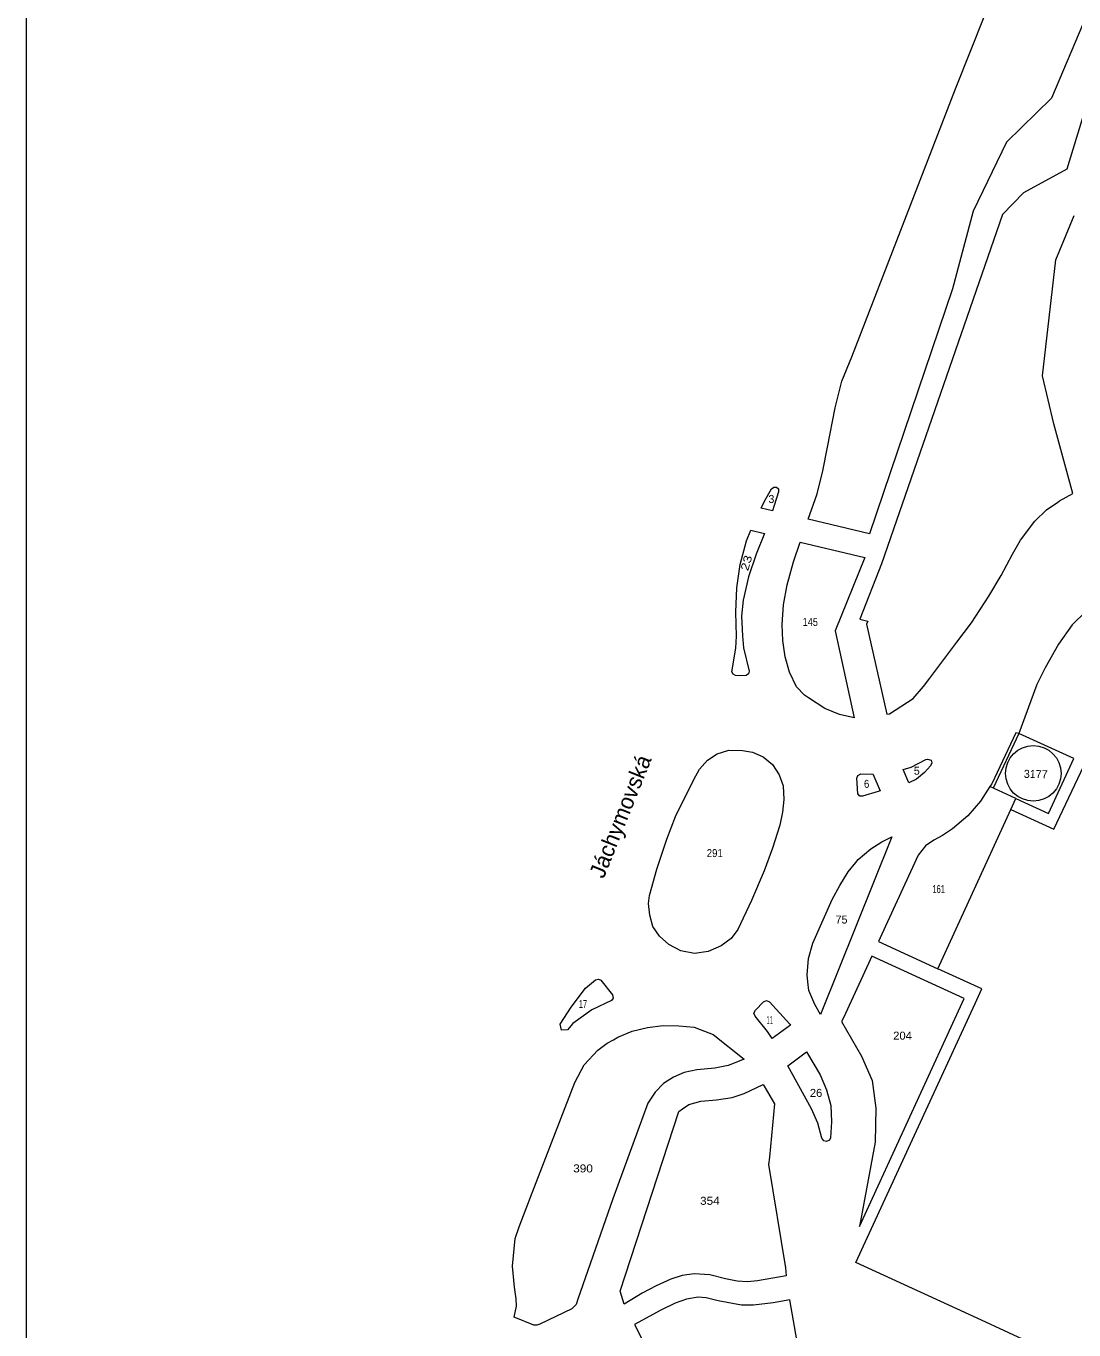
# Model space of a CAD drawing. Extents: x -843400 to -842830, y -1002860 to -1002082.
# Drawn here: x -843400.1 to -843269.1, y -1002620.7 to -1002457.7 of the extents above; entities that cross this region are included whole.
import ezdxf
from ezdxf.enums import TextEntityAlignment as Align

# ---------------------------------------------------------------- set-up
doc = ezdxf.new("R2010")
doc.units = 0
doc.header["$LTSCALE"] = 0.4
doc.layers.add('20', color=7, linetype='Continuous')
for name, color, linetype, lineweight in [('32', 7, 'Continuous', 13), ('35', 7, 'Continuous', 13), ('36', 7, 'Continuous', 13), ('38', 7, 'Continuous', 13), ('43', 7, 'Continuous', 13), ('44', 7, 'Continuous', 13)]:
    doc.layers.add(name, color=color, linetype=linetype, lineweight=lineweight)

msp = doc.modelspace()

# ---------------------------------------------------------------- linework, layer by layer
at = {"layer": '32'}
msp.add_lwpolyline([(-843229.79, -1002541.74), (-843230.26, -1002541.8), (-843232.13, -1002541.23), (-843242.89, -1002535.94), (-843244.35, -1002531.36), (-843249.31, -1002529.54), (-843252.84, -1002528.66), (-843256.77, -1002528.18), (-843260.3, -1002528.06), (-843262.55, -1002528.32), (-843264.95, -1002529.25), (-843267.58, -1002530.82), (-843269.35, -1002532.51), (-843271.05, -1002534.95), (-843272.73, -1002537.9), (-843273.74, -1002539.98), (-843276.02, -1002546.1), (-843276.39, -1002546.03), (-843279.4, -1002552.38), (-843279.629, -1002552.744)], dxfattribs=at)
at = {"layer": '36'}
msp.add_circle((-843274.196, -1002551.0828), 3.4752, dxfattribs=at)
at = {"layer": '38'}
for points in [[(-843276.364, -1002554.235), (-843272.28, -1002556.1), (-843269.15, -1002549.23), (-843276.02, -1002546.1), (-843279.2, -1002552.94)], [(-843276.99, -1002555.6), (-843271.63, -1002558.06), (-843267.9, -1002550.12), (-843233.22, -1002566.07), (-843229.49, -1002557.91), (-843217.51, -1002563.41), (-843214.18, -1002568.18), (-843216.63, -1002573.61), (-843205.49, -1002578.73), (-843233.93, -1002640.83), (-843246.1, -1002635.37), (-843247.52, -1002638.46), (-843254.81, -1002635.1), (-843253.51, -1002632), (-843281.23, -1002619.2), (-843296.36, -1002612.22), (-843281.484, -1002579.845), (-843280.65, -1002578.03), (-843286.12, -1002575.52)]]:
    msp.add_lwpolyline(points, dxfattribs=at)
at = {"layer": '43'}
for points in [[(-843217.19, -1002333.18), (-843226.47, -1002357.28), (-843239.13, -1002388.59), (-843250.24, -1002414.68), (-843261.68, -1002442.44), (-843271.91, -1002466.67), (-843277.55, -1002472.17), (-843281.73, -1002480.82), (-843284.3, -1002490.53), (-843294.657, -1002521.152), (-843302.333, -1002519.323), (-843301.23, -1002516.16), (-843300.52, -1002513.26), (-843299.93, -1002510.29), (-843298.98, -1002505.38), (-843298.14, -1002502.05), (-843296.89, -1002499.02), (-843283.93, -1002465.53), (-843273.11, -1002438.25), (-843261.95, -1002409.61), (-843251.14, -1002382.13), (-843240.02, -1002353.81), (-843228.82, -1002325.16)], [(-843265.4, -1002460.44), (-843269.723, -1002474.597), (-843270.02, -1002475.57), (-843275.43, -1002478.53), (-843278.04, -1002481.24), (-843293.19, -1002524.91), (-843295.89, -1002531.79), (-843294.89, -1002532.07), (-843295.03, -1002532.42), (-843292.51, -1002543.7), (-843292.17, -1002543.64), (-843289.21, -1002541.71), (-843287.93, -1002540.24), (-843287.14, -1002539.18), (-843283.77, -1002534.69), (-843281.94, -1002532.27), (-843279.74, -1002528.93), (-843278.22, -1002526.33), (-843276.8, -1002523.67), (-843275.81, -1002521.95), (-843274, -1002519.56), (-843272.55, -1002518.16), (-843271.14, -1002517.18), (-843270.91, -1002517.02), (-843269.25, -1002516.08), (-843269.62, -1002514.74), (-843271.64, -1002507.39), (-843273.057, -1002501.387), (-843271.39, -1002486.91), (-843269.09, -1002481.33)]]:
    msp.add_lwpolyline(points, dxfattribs=at)
for points in [[(-843308.215, -1002517.921), (-843307.78, -1002517.06), (-843306.93, -1002515.52), (-843306.65, -1002515.29), (-843306.3, -1002515.3), (-843306.05, -1002515.52), (-843306.04, -1002515.9), (-843306.58, -1002517.6), (-843306.806, -1002518.256)], [(-843310.84, -1002524.97), (-843310.05, -1002522.02), (-843309.517, -1002520.694), (-843307.799, -1002521.104), (-843308.84, -1002523.69), (-843309.81, -1002526.53), (-843310.45, -1002529.45), (-843310.65, -1002531.43), (-843310.56, -1002533.89), (-843310.4, -1002535.38), (-843309.73, -1002538.3), (-843309.81, -1002538.64), (-843310.09, -1002538.83), (-843310.77, -1002538.88), (-843311.41, -1002538.86), (-843311.73, -1002538.69), (-843311.86, -1002538.38), (-843311.38, -1002535.42), (-843311.3, -1002533.95), (-843311.38, -1002530.92), (-843311.24, -1002527.91)], [(-843303.326, -1002522.17), (-843295.266, -1002524.091), (-843298.95, -1002533.28), (-843296.58, -1002544.14), (-843298.44, -1002543.73), (-843300.26, -1002542.96), (-843302.3, -1002541.65), (-843302.8, -1002541.32), (-843303.8, -1002540.27), (-843304.66, -1002538.45), (-843305.2, -1002536.52), (-843305.52, -1002534.49), (-843305.6, -1002532.49), (-843305.42, -1002530.01), (-843304.98, -1002527.52), (-843304.19, -1002524.65)], [(-843305.96, -1002551.26), (-843305.48, -1002552.63), (-843305.36, -1002554.35), (-843305.53, -1002555.95), (-843305.9, -1002557.54), (-843306.81, -1002560.44), (-843307.83, -1002563.26), (-843309.4, -1002566.99), (-843311.12, -1002570.58), (-843311.961, -1002571.74), (-843313.22, -1002572.63), (-843314.82, -1002573.33), (-843316.56, -1002573.59), (-843318.27, -1002573.26), (-843319.76, -1002572.46), (-843320.9, -1002571.45), (-843321.76, -1002570.23), (-843322.14, -1002568.8), (-843322.29, -1002567.33), (-843322.19, -1002566.36), (-843321.25, -1002563.05), (-843320.02, -1002559.3), (-843318.93, -1002556.48), (-843316.61, -1002551.84), (-843315.93, -1002550.54), (-843314.94, -1002549.44), (-843313.71, -1002548.63), (-843312.27, -1002548.19), (-843310.55, -1002548.22), (-843309.3, -1002548.44), (-843307.96, -1002549), (-843306.81, -1002549.98)], [(-843290.45, -1002550.6), (-843289.47, -1002550.29), (-843287.63, -1002549.33), (-843287.44, -1002549.3), (-843286.97, -1002549.45), (-843286.86, -1002549.77), (-843287.03, -1002550.15), (-843287.78, -1002550.97), (-843288.8, -1002551.79), (-843289.74, -1002552.26)], [(-843293.333, -1002553.27), (-843293.57, -1002553.33), (-843295.53, -1002553.94), (-843295.89, -1002553.93), (-843296.11, -1002553.63), (-843296.27, -1002551.68), (-843296.14, -1002551.33), (-843295.76, -1002551.12), (-843294.37, -1002551.17), (-843294.235, -1002551.16)], [(-843286.12, -1002575.52), (-843276.99, -1002555.6), (-843276.364, -1002554.235), (-843279.629, -1002552.744), (-843280.78, -1002554.57), (-843282.4, -1002556.37), (-843284.31, -1002558.01), (-843285.54, -1002558.84), (-843286.63, -1002559.45), (-843287.68, -1002560.14), (-843288.59, -1002561.29), (-843293.11, -1002571.17), (-843293.547, -1002572.116)], [(-843291.88, -1002559.03), (-843300.79, -1002581.214), (-843301.5, -1002579.98), (-843302.24, -1002578.21), (-843302.37, -1002577.12), (-843302.48, -1002576.27), (-843302.3, -1002574.21), (-843301.74, -1002572.3), (-843299.35, -1002566.84), (-843298.39, -1002565.08), (-843297.33, -1002563.38), (-843296.39, -1002562.23), (-843296.08, -1002561.85), (-843294.51, -1002560.5), (-843293.12, -1002559.65)], [(-843282.848, -1002579.22), (-843294.386, -1002573.932), (-843294.81, -1002574.85), (-843297.94, -1002581.63), (-843298.162, -1002582.112), (-843295.69, -1002586.432), (-843294.333, -1002589.471), (-843293.892, -1002592.917), (-843293.956, -1002597.164), (-843295.937, -1002607.708)], [(-843333.17, -1002583.18), (-843333.32, -1002582.45), (-843331.98, -1002580.29), (-843330.19, -1002577.93), (-843328.9, -1002576.87), (-843328.55, -1002576.79), (-843328.24, -1002576.94), (-843326.79, -1002578.76), (-843326.7, -1002579.17), (-843326.94, -1002579.49), (-843329.36, -1002580.62), (-843331.75, -1002582.35), (-843332.44, -1002583.14)], [(-843304.56, -1002582.57), (-843306.85, -1002584.22), (-843307.42, -1002583.34), (-843308.96, -1002581.44), (-843309.11, -1002581.07), (-843308.94, -1002580.69), (-843307.92, -1002579.66), (-843307.56, -1002579.49), (-843307.17, -1002579.63), (-843304.63, -1002582.45)], [(-843315.84, -1002583.1), (-843314.23, -1002583.73), (-843310.33, -1002586.8), (-843312.33, -1002587.6), (-843314.02, -1002587.94), (-843316.27, -1002588.14), (-843317.82, -1002588.48), (-843319.19, -1002589.04), (-843320.42, -1002589.86), (-843321.48, -1002590.95), (-843322.37, -1002592.3), (-843326.76, -1002604.25), (-843331.13, -1002616.8), (-843331.35, -1002617.48), (-843331.87, -1002618.03), (-843335.86, -1002619.92), (-843336.25, -1002620.06), (-843336.61, -1002620.04), (-843339.1, -1002619.06), (-843338.81, -1002617.69), (-843338.85, -1002616.75), (-843339.06, -1002615.29), (-843339.28, -1002612.68), (-843338.96, -1002609.24), (-843338.48, -1002607.78), (-843337.05, -1002604.04), (-843335.12, -1002599.1), (-843331.5, -1002589.71), (-843330.32, -1002587.51), (-843328.64, -1002585.67), (-843327.46, -1002584.81), (-843326.68, -1002584.38), (-843326.14, -1002584.07), (-843324.35, -1002583.32), (-843322.43, -1002582.84), (-843320.48, -1002582.59), (-843318.52, -1002582.62), (-843316.59, -1002582.81)], [(-843302.53, -1002585.9), (-843300.84, -1002588.78), (-843300.04, -1002590.65), (-843299.52, -1002592.61), (-843299.44, -1002594.62), (-843299.53, -1002596.62), (-843299.67, -1002596.93), (-843300.03, -1002597.1), (-843300.39, -1002597.03), (-843300.63, -1002596.7), (-843301.14, -1002594.8), (-843301.92, -1002593), (-843304.89, -1002587.65)], [(-843318.52, -1002593.34), (-843318.03, -1002593), (-843317.26, -1002592.47), (-843315.77, -1002592.07), (-843313.81, -1002591.91), (-843311.85, -1002591.58), (-843310.34, -1002591.09), (-843307.97, -1002589.97), (-843307.44, -1002590.87), (-843306.53, -1002592.4), (-843307.19, -1002599.06), (-843307.28, -1002599.97), (-843305.19, -1002612.89), (-843305.07, -1002613.89), (-843308.69, -1002614.51), (-843309.94, -1002614.62), (-843311.21, -1002614.57), (-843312.68, -1002614.27), (-843314.62, -1002613.77), (-843316.59, -1002613.63), (-843318.1, -1002613.84), (-843319.49, -1002614.3), (-843321.34, -1002615.14), (-843323.1, -1002616.06), (-843325.33, -1002617.43), (-843325.85, -1002615.8)], [(-843296.15, -1002651.57), (-843299.74, -1002646.72), (-843303.02, -1002626.16), (-843304.63, -1002616.89), (-843306.72, -1002617.26), (-843309.18, -1002617.56), (-843310.69, -1002617.56), (-843313.59, -1002617.01), (-843315.08, -1002616.64), (-843316.08, -1002616.56), (-843317.56, -1002616.79), (-843318.98, -1002617.3), (-843320.76, -1002618.18), (-843324.05, -1002619.99), (-843315.52, -1002637.02), (-843307.41, -1002653.43), (-843302.74, -1002658.55), (-843296.19, -1002662.79), (-843284.8, -1002667.54), (-843278.01, -1002669.84), (-843275.318, -1002663.859), (-843274.325, -1002661.635)]]:
    msp.add_lwpolyline(points, close=True, dxfattribs=at)
at = {"layer": '44'}
msp.add_lwpolyline([(-842830.097, -1002859.997), (-842830.097, -1002081.989), (-843400.094, -1002081.989), (-843400.094, -1002859.997)], close=True, dxfattribs=at)

# ---------------------------------------------------------------- texts
at = {"layer": '20'}
msp.add_text('Jáchymovská', height=2, rotation=68.169, dxfattribs=at).set_placement((-843327.903, -1002564.336))
at = {"layer": '35'}
msp.add_text('3177', height=1, rotation=358.734, dxfattribs=at).set_placement((-843273.903, -1002551.6718), align=Align.CENTER)
at = {"layer": '43'}
for s, p in [('3', (-843307.309, -1002517.278)), ('5', (-843289.135, -1002551.253)), ('75', (-843298.91, -1002569.855))]:
    msp.add_text(s, height=1, dxfattribs=at).set_placement(p)
at = {"layer": '43', "width": 1.3}
msp.add_text('23', height=1, rotation=73.836, dxfattribs=at).set_placement((-843309.855, -1002525.845))
at = {"layer": '43'}
for s, width, p in [('145', 0.85, (-843303.019, -1002532.656)), ('6', 0.9, (-843295.362, -1002552.892)), ('291', 0.9, (-843315.017, -1002561.548)), ('161', 0.65, (-843286.817, -1002566.049)), ('17', 0.7, (-843331.008, -1002580.411)), ('11', 0.45, (-843307.561, -1002582.422)), ('204', 1.05, (-843291.714, -1002584.366)), ('26', 1.05, (-843302.129, -1002591.522)), ('390', 1.1, (-843331.705, -1002600.962)), ('354', 1.1, (-843315.85, -1002605.012))]:
    msp.add_text(s, height=1, dxfattribs=dict(at, width=width)).set_placement(p)

doc.saveas('drawing.dxf')
